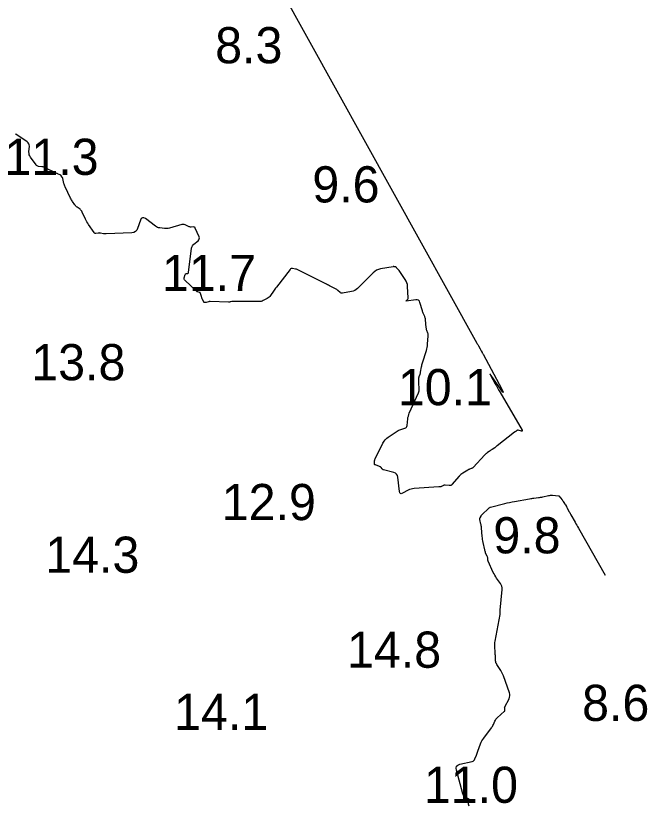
# Model space of a CAD drawing. Extents: x 815352 to 820877, y 582403 to 597439.
# Drawn here: x 819802.8 to 819890.1, y 593408.5 to 593517.5 of the extents above; entities that cross this region are included whole.
import ezdxf

# ---------------------------------------------------------------- set-up
doc = ezdxf.new("R2010")
doc.units = 0
doc.layers.add('V-CONT-EL12', color=7, linetype='Continuous')
doc.layers.add('V-TOPO-SOUN', color=7, linetype='Continuous')

msp = doc.modelspace()

# ---------------------------------------------------------------- linework, layer by layer
at = {"layer": 'V-CONT-EL12'}
for points in [[(819819.87, 593556.3), (819866.53, 593472.22), (819866.58, 593472.13), (819866.64, 593472.04), (819866.69, 593471.95), (819866.74, 593471.86), (819866.98, 593471.43), (819867.01, 593471.37), (819867.05, 593471.31), (819867.08, 593471.25), (819867.11, 593471.19), (819867.25, 593470.95), (819867.28, 593470.89), (819867.32, 593470.83), (819867.35, 593470.77), (819867.38, 593470.71), (819869.97, 593465.86), (819870.14, 593465.52), (819870.18, 593465.4), (819870.09, 593465.49), (819869.87, 593465.8), (819868.51, 593467.76), (819868.38, 593467.95), (819868.32, 593468.01), (819868.35, 593467.93), (819868.46, 593467.73), (819869.07, 593466.62), (819869.22, 593466.35), (819869.37, 593466.07), (819869.53, 593465.8), (819869.69, 593465.52), (819872.78, 593460.2), (819872.81, 593460.13), (819872.81, 593460.09), (819872.77, 593460.07), (819872.7, 593460.08), (819872.25, 593460.19), (819872.2, 593460.2), (819872.15, 593460.19), (819872.11, 593460.18), (819872.07, 593460.16), (819871.91, 593460.04), (819871.87, 593460.02), (819871.83, 593459.99), (819871.79, 593459.96), (819871.75, 593459.93), (819869.34, 593458.04), (819869.25, 593457.98), (819869.16, 593457.91), (819869.08, 593457.85), (819868.99, 593457.79), (819868.62, 593457.55), (819868.53, 593457.49), (819868.45, 593457.43), (819868.36, 593457.37), (819868.28, 593457.31), (819867.94, 593457.07), (819867.86, 593457.01), (819867.78, 593456.95), (819867.71, 593456.88), (819867.63, 593456.8), (819866, 593455.07), (819865.95, 593455.02), (819865.9, 593454.98), (819865.84, 593454.94), (819865.78, 593454.92), (819865.52, 593454.82), (819865.45, 593454.79), (819865.39, 593454.76), (819865.33, 593454.73), (819865.27, 593454.69), (819864.57, 593454.27), (819864.44, 593454.19), (819864.32, 593454.09), (819864.2, 593453.99), (819864.09, 593453.87), (819863.08, 593452.71), (819863, 593452.63), (819862.91, 593452.58), (819862.82, 593452.56), (819862.71, 593452.56), (819862.16, 593452.61), (819862.1, 593452.61), (819862.04, 593452.61), (819861.98, 593452.59), (819861.92, 593452.56), (819861.64, 593452.42), (819861.61, 593452.41), (819861.58, 593452.4), (819861.55, 593452.39), (819861.52, 593452.39), (819861.38, 593452.39), (819861.35, 593452.39), (819861.32, 593452.39), (819861.28, 593452.39), (819861.25, 593452.38), (819857.85, 593452.14), (819857.63, 593452.11), (819857.42, 593452.07), (819857.22, 593452), (819857.02, 593451.9), (819856.25, 593451.49), (819856.08, 593451.43), (819855.95, 593451.45), (819855.87, 593451.55), (819855.82, 593451.72), (819855.6, 593453.73), (819855.54, 593453.96), (819855.43, 593454.15), (819855.26, 593454.29), (819855.03, 593454.38), (819853.63, 593454.73), (819853.58, 593454.75), (819853.53, 593454.78), (819853.48, 593454.82), (819853.44, 593454.86), (819853.28, 593455.05), (819853.23, 593455.09), (819853.19, 593455.13), (819853.14, 593455.16), (819853.08, 593455.19), (819852.49, 593455.4), (819852.43, 593455.44), (819852.39, 593455.48), (819852.36, 593455.54), (819852.36, 593455.61), (819852.38, 593455.93), (819852.39, 593456.01), (819852.41, 593456.08), (819852.43, 593456.15), (819852.47, 593456.23), (819853.54, 593458.42), (819853.69, 593458.67), (819853.86, 593458.89), (819854.06, 593459.09), (819854.28, 593459.26), (819855.49, 593460.07), (819855.62, 593460.15), (819855.75, 593460.22), (819855.88, 593460.28), (819856.02, 593460.32), (819856.58, 593460.49), (819856.7, 593460.55), (819856.8, 593460.63), (819856.86, 593460.74), (819856.89, 593460.87), (819856.97, 593461.78), (819857, 593461.97), (819857.05, 593462.17), (819857.1, 593462.36), (819857.18, 593462.54), (819858.46, 593465.37), (819858.51, 593465.51), (819858.55, 593465.66), (819858.56, 593465.81), (819858.56, 593465.96), (819858.49, 593466.71), (819858.49, 593466.79), (819858.49, 593466.87), (819858.49, 593466.94), (819858.49, 593467.02), (819858.5, 593467.33), (819858.51, 593467.4), (819858.52, 593467.48), (819858.54, 593467.55), (819858.56, 593467.63), (819858.67, 593467.93), (819858.69, 593468.01), (819858.72, 593468.08), (819858.73, 593468.16), (819858.75, 593468.24), (819858.87, 593468.96), (819858.9, 593469.1), (819858.93, 593469.25), (819858.97, 593469.39), (819859.01, 593469.53), (819859.55, 593471.22), (819859.61, 593471.43), (819859.66, 593471.65), (819859.7, 593471.87), (819859.72, 593472.09), (819859.8, 593473.25), (819859.8, 593473.34), (819859.79, 593473.43), (819859.77, 593473.52), (819859.74, 593473.61), (819859.61, 593473.97), (819859.58, 593474.06), (819859.56, 593474.15), (819859.54, 593474.24), (819859.53, 593474.34), (819859.41, 593475.52), (819859.4, 593475.62), (819859.37, 593475.72), (819859.34, 593475.82), (819859.31, 593475.92), (819859.14, 593476.3), (819859.09, 593476.4), (819859.06, 593476.5), (819859.02, 593476.6), (819858.99, 593476.7), (819858.66, 593477.85), (819858.58, 593478.05), (819858.45, 593478.18), (819858.28, 593478.24), (819858.07, 593478.23), (819856.77, 593478.03), (819856.72, 593478.03), (819856.69, 593478.04), (819856.7, 593478.06), (819856.74, 593478.1), (819856.95, 593478.28), (819856.99, 593478.33), (819857.02, 593478.39), (819857.04, 593478.45), (819857.04, 593478.51), (819856.95, 593480.06), (819856.92, 593480.32), (819856.85, 593480.57), (819856.75, 593480.8), (819856.62, 593481.03), (819855.78, 593482.26), (819855.74, 593482.3), (819855.71, 593482.35), (819855.68, 593482.39), (819855.64, 593482.43), (819855.43, 593482.66), (819855.41, 593482.68), (819855.39, 593482.7), (819855.36, 593482.74), (819855.35, 593482.75), (819855.34, 593482.76), (819855.33, 593482.76), (819855.31, 593482.77), (819855.09, 593482.8), (819855.05, 593482.81), (819855.01, 593482.81), (819854.97, 593482.81), (819854.93, 593482.8), (819853.22, 593482.5), (819852.93, 593482.43), (819852.66, 593482.31), (819852.42, 593482.16), (819852.19, 593481.97), (819850.01, 593479.78), (819849.83, 593479.63), (819849.64, 593479.5), (819849.42, 593479.41), (819849.19, 593479.36), (819847.96, 593479.14), (819847.86, 593479.14), (819847.77, 593479.15), (819847.69, 593479.19), (819847.61, 593479.24), (819847.31, 593479.51), (819847.24, 593479.58), (819847.16, 593479.63), (819847.07, 593479.69), (819846.99, 593479.74), (819846.31, 593480.08), (819846.16, 593480.16), (819846.02, 593480.23), (819845.88, 593480.3), (819845.73, 593480.37), (819841.87, 593482.32), (819841.77, 593482.37), (819841.67, 593482.41), (819841.57, 593482.44), (819841.46, 593482.46), (819841.03, 593482.55), (819840.93, 593482.56), (819840.84, 593482.54), (819840.76, 593482.49), (819840.69, 593482.42), (819838.8, 593479.96), (819838.7, 593479.82), (819838.6, 593479.69), (819838.5, 593479.55), (819838.4, 593479.4), (819838, 593478.81), (819837.9, 593478.69), (819837.79, 593478.58), (819837.67, 593478.49), (819837.54, 593478.41), (819836.99, 593478.12), (819836.85, 593478.05), (819836.7, 593478.01), (819836.55, 593477.98), (819836.4, 593477.97), (819832.86, 593477.99), (819832.81, 593477.99), (819832.75, 593477.98), (819832.69, 593477.98), (819832.64, 593477.97), (819832.42, 593477.93), (819832.36, 593477.92), (819832.3, 593477.91), (819832.25, 593477.91), (819832.19, 593477.91), (819829.64, 593477.98), (819829.58, 593477.98), (819829.52, 593477.97), (819829.46, 593477.96), (819829.4, 593477.95), (819829.11, 593477.86), (819829.08, 593477.85), (819829.04, 593477.84), (819829.01, 593477.84), (819828.98, 593477.84), (819828.84, 593477.86), (819828.81, 593477.87), (819828.79, 593477.88), (819828.76, 593477.9), (819828.75, 593477.93), (819828.55, 593478.38), (819828.51, 593478.46), (819828.48, 593478.54), (819828.45, 593478.62), (819828.43, 593478.7), (819828.33, 593479.09), (819828.31, 593479.15), (819828.28, 593479.19), (819828.24, 593479.22), (819828.18, 593479.24), (819827.95, 593479.31), (819827.89, 593479.33), (819827.84, 593479.35), (819827.79, 593479.38), (819827.75, 593479.42), (819826.16, 593480.93), (819826.1, 593481), (819826.06, 593481.08), (819826.05, 593481.16), (819826.07, 593481.26), (819826.2, 593481.73), (819826.22, 593481.77), (819826.25, 593481.81), (819826.29, 593481.83), (819826.33, 593481.85), (819826.54, 593481.88), (819826.59, 593481.89), (819826.62, 593481.92), (819826.64, 593481.95), (819826.66, 593482), (819827.08, 593485.34), (819827.12, 593485.51), (819827.18, 593485.67), (819827.28, 593485.81), (819827.4, 593485.93), (819827.97, 593486.38), (819828.08, 593486.5), (819828.14, 593486.63), (819828.15, 593486.78), (819828.11, 593486.94), (819827.59, 593488.13), (819827.55, 593488.2), (819827.5, 593488.25), (819827.43, 593488.28), (819827.35, 593488.29), (819827, 593488.28), (819826.91, 593488.28), (819826.82, 593488.3), (819826.74, 593488.32), (819826.66, 593488.35), (819826.18, 593488.57), (819826.07, 593488.61), (819825.96, 593488.63), (819825.85, 593488.63), (819825.74, 593488.61), (819824.01, 593488.13), (819823.84, 593488.09), (819823.68, 593488.07), (819823.51, 593488.07), (819823.34, 593488.08), (819822.67, 593488.16), (819822.51, 593488.19), (819822.36, 593488.24), (819822.21, 593488.31), (819822.07, 593488.4), (819820.69, 593489.44), (819820.46, 593489.57), (819820.27, 593489.57), (819820.12, 593489.46), (819820, 593489.23), (819819.61, 593488.08), (819819.49, 593487.83), (819819.32, 593487.65), (819819.09, 593487.53), (819818.81, 593487.48), (819815.28, 593487.33), (819815.18, 593487.33), (819815.09, 593487.33), (819814.99, 593487.34), (819814.9, 593487.36), (819814.49, 593487.44), (819814.41, 593487.45), (819814.33, 593487.46), (819814.25, 593487.45), (819814.17, 593487.45), (819813.85, 593487.4), (819813.77, 593487.4), (819813.7, 593487.41), (819813.64, 593487.45), (819813.59, 593487.51), (819812.83, 593488.62), (819812.71, 593488.81), (819812.6, 593489), (819812.49, 593489.19), (819812.4, 593489.39), (819811.94, 593490.36), (819811.88, 593490.47), (819811.81, 593490.56), (819811.73, 593490.65), (819811.65, 593490.73), (819811.27, 593491.02), (819811.18, 593491.09), (819811.09, 593491.18), (819811.01, 593491.27), (819810.94, 593491.36), (819810.62, 593491.81), (819810.55, 593491.92), (819810.48, 593492.03), (819810.41, 593492.15), (819810.35, 593492.27), (819809.59, 593493.84), (819809.53, 593493.95), (819809.49, 593494.07), (819809.45, 593494.2), (819809.41, 593494.32), (819809.26, 593494.98), (819809.25, 593495.03), (819809.23, 593495.08), (819809.21, 593495.13), (819809.18, 593495.18), (819809.06, 593495.36), (819809.02, 593495.4), (819808.99, 593495.44), (819808.94, 593495.47), (819808.89, 593495.5), (819808.62, 593495.61), (819808.56, 593495.64), (819808.5, 593495.66), (819808.43, 593495.69), (819808.37, 593495.72), (819806.75, 593496.51), (819806.65, 593496.55), (819806.55, 593496.58), (819806.45, 593496.61), (819806.35, 593496.62), (819805.92, 593496.66), (819805.82, 593496.68), (819805.73, 593496.72), (819805.65, 593496.78), (819805.58, 593496.86), (819804.8, 593497.95), (819804.7, 593498.11), (819804.63, 593498.28), (819804.6, 593498.46), (819804.59, 593498.66), (819804.64, 593499.44), (819804.63, 593499.62), (819804.57, 593499.79), (819804.48, 593499.93), (819804.34, 593500.05), (819802.77, 593501.12), (819802.72, 593501.15)], [(819865.44, 593408.26), (819865.37, 593408.54), (819865.37, 593408.6), (819865.37, 593408.66), (819865.38, 593408.71), (819865.4, 593408.77), (819865.49, 593408.98), (819865.51, 593409.04), (819865.5, 593409.08), (819865.48, 593409.12), (819865.44, 593409.16), (819864.88, 593409.56), (819864.78, 593409.65), (819864.7, 593409.75), (819864.63, 593409.86), (819864.59, 593409.98), (819863.69, 593413.23), (819863.65, 593413.52), (819863.72, 593413.76), (819863.89, 593413.93), (819864.17, 593414.04), (819865.87, 593414.44), (819866, 593414.49), (819866.1, 593414.56), (819866.19, 593414.66), (819866.26, 593414.78), (819866.47, 593415.32), (819866.52, 593415.46), (819866.58, 593415.59), (819866.63, 593415.73), (819866.68, 593415.87), (819867.04, 593416.88), (819867.12, 593417.09), (819867.22, 593417.29), (819867.34, 593417.48), (819867.47, 593417.66), (819868.53, 593419.06), (819868.61, 593419.17), (819868.68, 593419.28), (819868.75, 593419.4), (819868.81, 593419.52), (819869.02, 593420.02), (819869.08, 593420.15), (819869.15, 593420.26), (819869.24, 593420.36), (819869.33, 593420.46), (819870.34, 593421.37), (819870.37, 593421.4), (819870.39, 593421.45), (819870.4, 593421.5), (819870.4, 593421.55), (819870.37, 593421.77), (819870.36, 593421.82), (819870.37, 593421.88), (819870.38, 593421.93), (819870.4, 593421.98), (819870.98, 593423.09), (819871.06, 593423.3), (819871.1, 593423.51), (819871.09, 593423.72), (819871.03, 593423.93), (819870.19, 593426.25), (819870.11, 593426.45), (819870.03, 593426.64), (819869.93, 593426.82), (819869.82, 593427), (819869.3, 593427.82), (819869.23, 593427.95), (819869.17, 593428.08), (819869.14, 593428.21), (819869.12, 593428.35), (819869.09, 593428.93), (819869.08, 593429.08), (819869.07, 593429.22), (819869.06, 593429.37), (819869.05, 593429.51), (819869.01, 593430.32), (819869.01, 593430.51), (819869.01, 593430.69), (819869.03, 593430.87), (819869.06, 593431.05), (819869.77, 593434.74), (819869.77, 593434.75), (819869.77, 593434.75), (819869.77, 593434.76), (819869.77, 593434.77), (819869.77, 593434.8), (819869.77, 593434.81), (819869.77, 593434.82), (819869.77, 593434.83), (819869.77, 593434.84), (819869.77, 593435.13), (819869.77, 593435.19), (819869.77, 593435.24), (819869.77, 593435.29), (819869.77, 593435.34), (819870.02, 593438.21), (819870.02, 593438.43), (819869.98, 593438.65), (819869.9, 593438.85), (819869.79, 593439.04), (819869.26, 593439.78), (819869.13, 593439.96), (819869.01, 593440.16), (819868.9, 593440.36), (819868.8, 593440.56), (819868.1, 593442.09), (819868.08, 593442.15), (819868.06, 593442.2), (819868.05, 593442.25), (819868.04, 593442.31), (819868.02, 593442.53), (819868.02, 593442.59), (819868.01, 593442.64), (819867.99, 593442.7), (819867.97, 593442.75), (819867.74, 593443.26), (819867.7, 593443.37), (819867.66, 593443.47), (819867.63, 593443.58), (819867.61, 593443.69), (819867.4, 593444.7), (819867.35, 593444.9), (819867.32, 593445.11), (819867.29, 593445.32), (819867.27, 593445.53), (819867.16, 593446.73), (819867.15, 593446.86), (819867.13, 593446.99), (819867.11, 593447.12), (819867.08, 593447.24), (819866.94, 593447.87), (819866.93, 593447.93), (819866.93, 593447.99), (819866.94, 593448.06), (819866.97, 593448.12), (819867.1, 593448.35), (819867.13, 593448.41), (819867.17, 593448.47), (819867.21, 593448.52), (819867.26, 593448.57), (819868.15, 593449.41), (819868.17, 593449.43), (819868.18, 593449.44), (819868.21, 593449.46), (819868.23, 593449.47), (819868.31, 593449.53), (819868.34, 593449.54), (819868.36, 593449.55), (819868.38, 593449.56), (819868.41, 593449.57), (819870.39, 593450.07), (819870.72, 593450.16), (819871.06, 593450.23), (819871.41, 593450.3), (819871.75, 593450.37), (819873.81, 593450.74), (819873.97, 593450.76), (819874.12, 593450.79), (819874.27, 593450.81), (819874.42, 593450.83), (819875.03, 593450.89), (819875.19, 593450.91), (819875.34, 593450.94), (819875.49, 593450.96), (819875.64, 593451), (819876.43, 593451.17), (819876.57, 593451.19), (819876.71, 593451.21), (819876.85, 593451.21), (819876.99, 593451.21), (819877.82, 593451.14), (819877.82, 593451.14), (819877.83, 593451.14), (819877.83, 593451.15), (819877.84, 593451.15), (819877.86, 593451.16), (819877.87, 593451.16), (819877.87, 593451.16), (819877.88, 593451.16), (819877.88, 593451.16), (819878.32, 593450.57), (819878.36, 593450.51), (819878.4, 593450.46), (819878.44, 593450.4), (819878.48, 593450.34), (819878.64, 593450.1), (819878.68, 593450.04), (819878.71, 593449.99), (819878.75, 593449.94), (819878.78, 593449.88), (819878.91, 593449.67), (819878.94, 593449.61), (819878.97, 593449.56), (819879, 593449.5), (819879.03, 593449.45), (819879.31, 593448.92), (819879.36, 593448.82), (819879.42, 593448.71), (819879.48, 593448.61), (819879.53, 593448.5), (819880.1, 593447.5), (819880.21, 593447.29), (819880.33, 593447.09), (819880.44, 593446.89), (819880.56, 593446.69), (819884.25, 593440.19)]]:
    msp.add_lwpolyline(points, dxfattribs=at)

# ---------------------------------------------------------------- texts
at = {"layer": 'V-TOPO-SOUN'}
for s, p in [('8.3', (819830.34, 593510.91)), ('11.3 ', (819801.2, 593495.49)), ('9.6', (819843.77, 593491.68)), ('11.7 ', (819822.98, 593479.44)), ('13.8 ', (819804.91, 593467.11)), ('10.1 ', (819855.6, 593463.66)), ('12.9 ', (819831.25, 593447.78)), ('9.8', (819868.8, 593443.19)), ('14.3 ', (819806.84, 593440.5)), ('14.8 ', (819848.57, 593427.38)), ('8.6', (819881.08, 593420.03)), ('14.1 ', (819824.66, 593418.78)), ('11.0 ', (819859.2, 593408.71))]:
    msp.add_text(s, height=5, dxfattribs=at).set_placement(p)

doc.saveas('drawing.dxf')
